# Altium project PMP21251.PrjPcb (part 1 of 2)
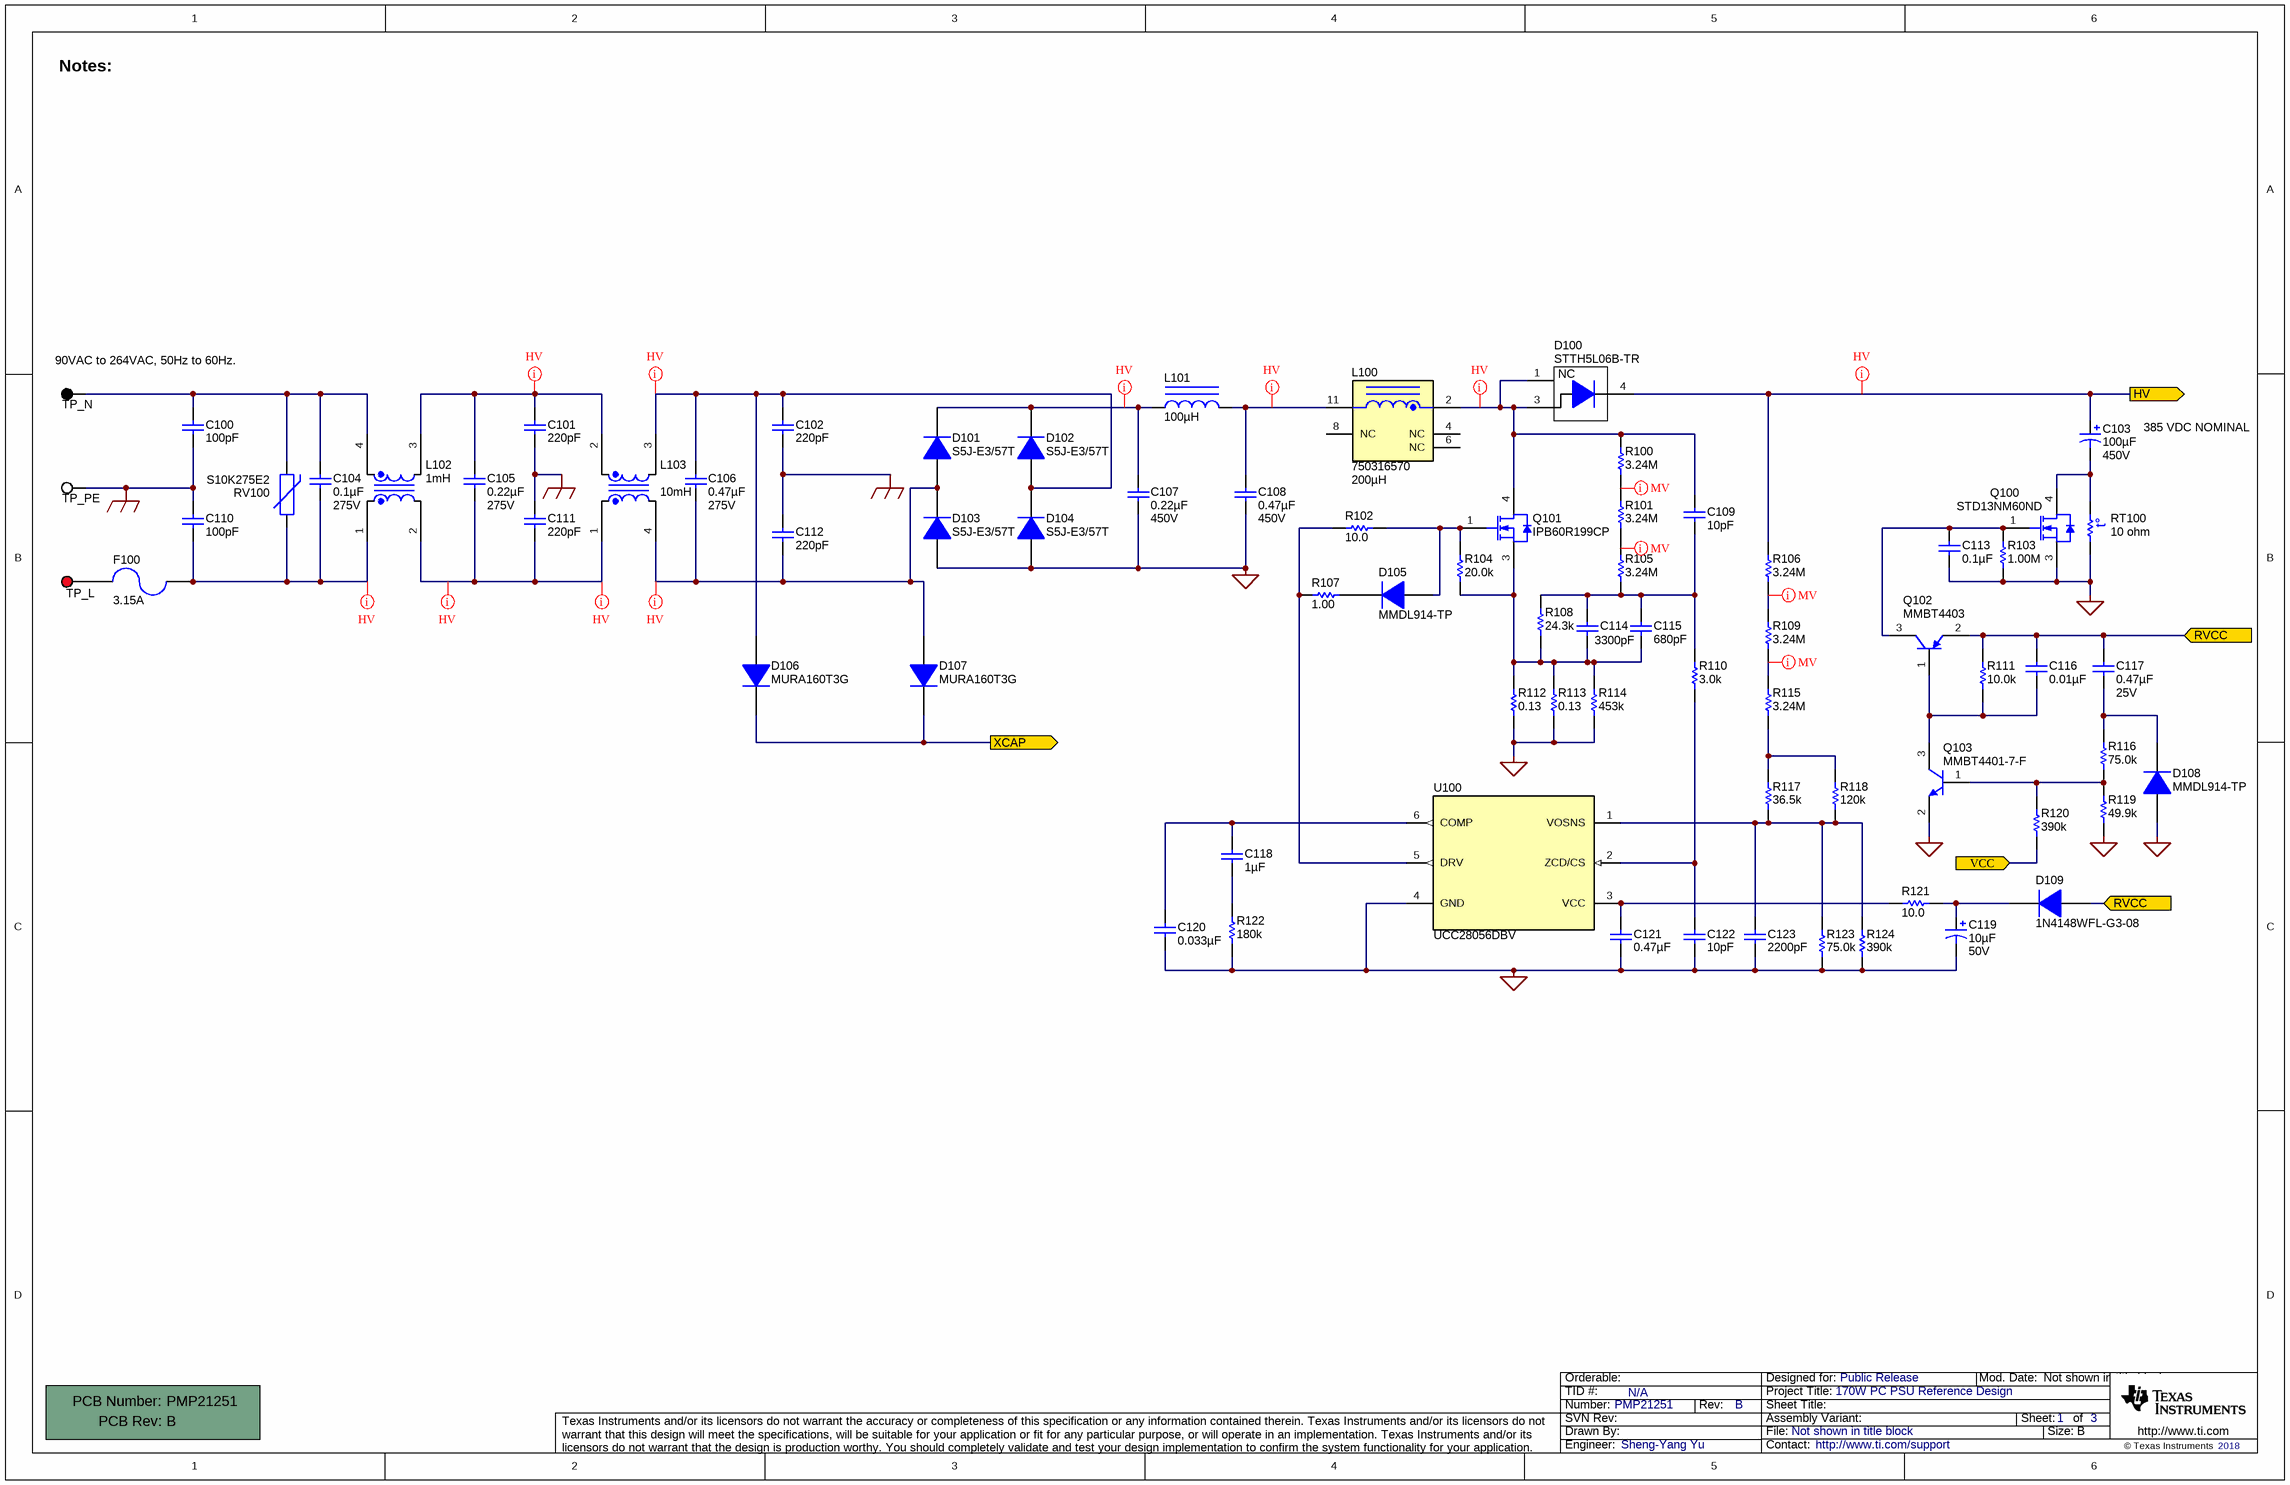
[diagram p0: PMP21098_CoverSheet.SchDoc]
CopyrightYear: 2018; PCB_Layout: Sheng-Yang Yu; PCB_Rev: B; PRJ_Customer: Public Release; PRJ_Engineer: Sheng-Yang Yu; PRJ_Number: PMP21251; PRJ_Title: 170W PC PSU Reference Design; SCH_Rev: B; TechSupport: http://www.ti.com/support; TID: N/A
3 sheets, 198 parts. Net scope: flat (ports and power ports of the same name join across sheets).
Board file: PMP21098_PCB.PcbDoc
Sheets:
  PMP21098_CoverSheet.SchDoc
  PMP21098_BlankSheet.SchDoc
  PMP21098_EVM_Hardware.SchDoc

## Sheet PMP21098_CoverSheet.SchDoc
size 431 x 279 mm; Date: Not shown in title block; ApprovedBy: Not shown in title block; CheckedBy: Not shown in title block; Author: Not shown in title block; CompanyName: Not shown in title block; Engineer: Not shown in title block; Organization: Not shown in title block; Address1: Not shown in title block; Address2: Not shown in title block; Address3: Not shown in title block; Address4: Not shown in title block; DocumentNumber: 1; Revision: Use project parameter SCH_Rev; SheetNumber: 1; SheetTotal: 3; PageSetup: Record=PageOptions¦CenterHorizontal=True¦CenterVertical=True¦PrintScale=1.00¦XCorrection=1.00¦YCorrection=1.00¦PrintKind=0¦BorderSize=5000000¦LeftOffset=0¦BottomOffset=0¦Orientation=2¦PaperLength=1000¦PaperWidth=1000¦Scale=100¦PaperSource=15¦PrintQuality=600¦MediaType=1¦DitherType=10¦PaperKind=Letter¦PrintScaleMode=1

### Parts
!PCB100  Printed Circuit Board  (value not drawn)  (mechanical)
C100  ValueDisplayed: 100pF  [DE1_600x400x900]  (hidden comment: DE1B3RA101KN4AN01F)
C101  ValueDisplayed: 220pF  [DE1_600x400x900]  (hidden comment: DE1B3RA101KN4AN01F)
C102  ValueDisplayed: 220pF  [DE1_600x400x900]  (hidden comment: DE1B3RA101KN4AN01F)
C103  ValueDisplayed: 100µF  Value2: 450V  [HXG_2200x4500]  (hidden comment: EKMQ451VSN101MP30S)
C104  ValueDisplayed: 0.1µF  VAC_X: 275V  [WCAP-FTX2_1300x700x1200]  (hidden comment: 890324023023CS)
C105  ValueDisplayed: 0.22µF  VAC_X: 275V  [WCAP-FTX2_1300x700x1200]  (hidden comment: 890324023028CS)
C106  ValueDisplayed: 0.47µF  VAC_X: 275V  [WCAP-FTX2_1500x1000x1600]  (hidden comment: 890324024005)
C107  ValueDisplayed: 0.22µF  Value2: 450V  [MPK_1800x650]  (hidden comment: ECW-FD2W224KQ)
C108  ValueDisplayed: 0.47µF  Value2: 450V  [MPK_1800x650]  (hidden comment: 450MPK474J)
C109  ValueDisplayed: 10pF  [0805_HV]  (hidden comment: VJ0805A100JXGAT5Z)
C110  ValueDisplayed: 100pF  [DE1_600x400x900]  (hidden comment: DE1B3RA101KN4AN01F)
C111  ValueDisplayed: 220pF  [DE1_600x400x900]  (hidden comment: DE1B3RA101KN4AN01F)
C112  ValueDisplayed: 220pF  [DE1_600x400x900]  (hidden comment: DE1B3RA101KN4AN01F)
C113  ValueDisplayed: 0.1µF  [0603]  (hidden comment: GRM188R61E104KA01D)
C114  ValueDisplayed: 3300pF  [0603]  (hidden comment: 06031C332JAT2A)
C115  ValueDisplayed: 680pF  [0603]  (hidden comment: GRM1885C1H681JA01D)
C116  ValueDisplayed: 0.01µF  [0603]  (hidden comment: 885012206040)
C117  ValueDisplayed: 0.47µF  Value2: 25V  [0805_HV]  (hidden comment: 08053D474KAT2A)
C118  ValueDisplayed: 1µF  [0603]  (hidden comment: C0603C105K3RACTU)
C119  ValueDisplayed: 10µF  Value2: 50V  [NHG_500x1100]  (hidden comment: ECA-1HHG100)
C120  ValueDisplayed: 0.033µF  [0603]  (hidden comment: C0603C333J3RACTU)
C121  ValueDisplayed: 0.47µF  [1206_180]  (hidden comment: CGA5L2X7R1H474K160AA)
C122  ValueDisplayed: 10pF  [0603]  (hidden comment: 0603ZC100KAT2A)
C123  ValueDisplayed: 2200pF  [0603]  (hidden comment: C0603C222K5RACTU)
D100  STTH5L06B-TR  [DPAK]
D101  S5J-E3/57T  [SMC]
D102  S5J-E3/57T  [SMC]
D103  S5J-E3/57T  [SMC]
D104  S5J-E3/57T  [SMC]
D105  MMDL914-TP  [SOD-323]
D106  MURA160T3G  [SMA]
D107  MURA160T3G  [SMA]
D108  MMDL914-TP  [SOD-323]
D109  1N4148WFL-G3-08  [SOD-123FL]
F100  Irating_A: 3.15A  [FUSE_372]  (hidden comment: 37213150001)
L100  750316570  ValueDisplayed: 200µH  [750316570]
L101  ValueDisplayed: 100µH  [IND_7447020]  (hidden comment: 7447021)
L102  ValueDisplayed: 1mH  [WE-CMB_XS]  (hidden comment: 744821201)
L103  ValueDisplayed: 10mH  [WE-CMB_M]  (hidden comment: 744823210)
Q100  STD13NM60ND  [DPAK]
Q101  IPB60R199CP  [DDPAK]
Q102  MMBT4403  [SOT-23]
Q103  MMBT4401-7-F  [SOT-23]
R100  ValueDisplayed: 3.24M  [1206]  (hidden comment: CRCW12063M24FKEA)
R101  ValueDisplayed: 3.24M  [1206]  (hidden comment: CRCW12063M24FKEA)
R102  ValueDisplayed: 10.0  [0603]  (hidden comment: CRCW060310R0FKEA)
R103  ValueDisplayed: 1.00M  [0603]  (hidden comment: CRCW06031M00FKEA)
R104  ValueDisplayed: 20.0k  [0805_HV]  (hidden comment: CRCW080520K0FKEA)
R105  ValueDisplayed: 3.24M  [1206]  (hidden comment: CRCW12063M24FKEA)
R106  ValueDisplayed: 3.24M  [1206]  (hidden comment: CRCW12063M24FKEA)
R107  ValueDisplayed: 1.00  [0603]  (hidden comment: CRCW06031R00FKEA)
R108  ValueDisplayed: 24.3k  [0603]  (hidden comment: CRCW060324K3FKEA)
R109  ValueDisplayed: 3.24M  [1206]  (hidden comment: CRCW12063M24FKEA)
R110  ValueDisplayed: 3.0k  [0603]  (hidden comment: CRCW06033K00JNEA)
R111  ValueDisplayed: 10.0k  [0603]  (hidden comment: CRCW060310K0FKEA)
R112  ValueDisplayed: 0.13  [1206]  (hidden comment: CSR1206FTR130)
R113  ValueDisplayed: 0.13  [1206]  (hidden comment: CSR1206FTR130)
R114  ValueDisplayed: 453k  [1206]  (hidden comment: CRCW1206453KFKEA)
R115  ValueDisplayed: 3.24M  [1206]  (hidden comment: CRCW12063M24FKEA)
R116  ValueDisplayed: 75.0k  [0603]  (hidden comment: CRCW060375K0FKEA)
R117  ValueDisplayed: 36.5k  [0603]  (hidden comment: CRCW060336K5FKEA)
R118  ValueDisplayed: 120k  [0603]  (hidden comment: RC0603FR-07120KL)
R119  ValueDisplayed: 49.9k  [0603]  (hidden comment: CRCW060349K9FKEA)
R120  ValueDisplayed: 390k  [0603]  (hidden comment: RC0603FR-07390KL)
R121  ValueDisplayed: 10.0  [0805_HV]  (hidden comment: CRCW080510R0FKEA)
R122  ValueDisplayed: 180k  [0603]  (hidden comment: RC0603FR-07180KL)
R123  ValueDisplayed: 75.0k  [0603]  (hidden comment: CRCW060375K0FKEA)
R124  ValueDisplayed: 390k  [0603]  (hidden comment: RC0603FR-07390KL)
RT100  value 10 ohm  [THERM_B57236S0]  (hidden comment: B57236S0100M000)
RV100  S10K275E2  [VAR_S10K275E2]
TP_L  5010  [Keystone5010]  (value not drawn)
TP_N  5011  [Keystone5011]  (value not drawn)
TP_PE  5012  [Keystone5012]  (value not drawn)
U100  UCC28056DBV  [DBV0006A_N]

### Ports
HV (out), RVCC (in), VCC (in), XCAP (out)

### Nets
GND: C107.1 C108.1 C113.2 C119.2(-) C120.2 C121.2 C122.2 C123.2 D103.2(A) D104.2(A) D108.2(A) Q100.3(S) Q103.2(E) R103.1 R112.1 R113.1 R114.1 R119.1 R122.1 R123.1 R124.1 RT100.1 U100.4(GND)
PE: C100.2 C101.2 C102.2 C110.1 C111.1 C112.1 TP_PE.1
HV: C103.1(+) D100.4(K) R106.2 ; port HV
RVCC: C116.1 C117.1 D109.2(A) Q102.2(E) R111.2 ; port RVCC
VCC: R120.1 ; port VCC
XCAP: D106.1(K) D107.1(K) ; port XCAP
NetC100_1: C100.1 C104.1 L102.4 RV100.2 TP_N.1
NetC101_1: C101.1 C105.1 L102.3 L103.2
NetC102_1: C102.1 C106.1 D102.2(A) D104.1(K) D106.2(A) L103.3
NetC103_2: C103.2(-) Q100.4(D) RT100.2
NetC104_2: C104.2 C110.2 F100.2 L102.1 RV100.1
NetC105_2: C105.2 C111.2 L102.2 L103.1
NetC106_2: C106.2 C112.2 D101.2(A) D103.1(K) D107.2(A) L103.4
NetC107_2: C107.2 D101.1(K) D102.1(K) L101.1
NetC108_2: C108.2 L100.11 L101.2
NetC109_1: C109.1 C114.1 C115.1 R105.1 R108.2 R110.1
NetC109_2: C109.2 D100.1(NC) D100.3(A) L100.2 Q101.4(D) R100.2
NetC113_1: C113.1 Q100.1(G) Q102.3(C) R103.2
NetC114_2: C114.2 C115.2 Q101.3(S) R104.1 R108.1 R112.2 R113.2 R114.2
NetC116_2: C116.2 Q102.1(B) Q103.3(C) R111.1
NetC117_2: C117.2 D108.1(K) R116.2
NetC118_1: C118.1 C120.1 U100.6(COMP)
NetC118_2: C118.2 R122.2
NetC119_1: C119.1(+) D109.1(K) R121.2
NetC121_1: C121.1 R121.1 U100.3(VCC)
NetC122_1: C122.1 R110.2 U100.2(ZCD/CS)
NetC123_1: C123.1 R117.1 R118.1 R123.2 R124.2 U100.1(VOSNS)
NetD105_1: D105.1(K) R107.2
NetD105_2: D105.2(A) Q101.1(G) R102.2 R104.2
NetF100_1: F100.1 TP_L.1
NetQ103_1: Q103.1(B) R116.1 R119.2 R120.2
NetR100_1: R100.1 R101.2
NetR101_1: R101.1 R105.2
NetR102_1: R102.1 R107.1 U100.5(DRV)
NetR106_1: R106.1 R109.2
NetR109_1: R109.1 R115.2
NetR115_1: R115.1 R117.2 R118.2

Not connected (* = marked no-connect by the designer): L100 4(NC) 6(NC) 8(NC)

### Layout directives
net class HV: HV, NetC101_1, NetC102_1, NetC104_2, NetC105_2, NetC106_2, NetC107_2, NetC108_2, NetC109_2
net class MV: (no net found under the mark), NetR100_1, NetR106_1, NetR109_1

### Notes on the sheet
- Notes:
- (near TP_N) 90VAC to 264VAC, 50Hz to 60Hz.
- 385 VDC NOMINAL

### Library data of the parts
!PCB100 = PCB: Manufacturer: Any; PartNumber: PMP21251; SymbolCreator: a0412235
C100 = CMP-0077651-2: CAP, CERM, 100 pF, X1 440 VAC/Y1 250 VAC, +/- 10%, B, D6xT4mm; Manufacturer: MuRata; TaMax_C: 125°C; SizeX_mm: 10.6; SizeY_mm: 4.0; TaMin_C: -40°C; CompType: Capacitor; SizeZ_mm: 9.0; AEC Qualified: N; Value: 100pF; SizeArea_mm2: 42.4; AEC Category: Q200; SizeAreaWB_mm2: 75.6; U/M: EA; Cap_Case: 6x4x9mm; AC_Safety: X1Y1; VAC_X: 440; VAC_Y: 250
C101 C102 C111 C112 = CMP-0077651-2: CAP CER 220PF 250V RAD; PartNumber: DE1B3RA221KN4AN01F; Manufacturer: MuRata; TaMax_C: 125°C; SizeX_mm: 10.6; SizeY_mm: 4.0; TaMin_C: -40°C; CompType: Capacitor; SizeZ_mm: 9.0; AEC Qualified: N; SizeArea_mm2: 42.4; AEC Category: Q200; SizeAreaWB_mm2: 75.6; U/M: EA; Tolerance_%: 10%; TempCo: B; Cap_Case: 6x4x9mm; Cap_F: 100pF; AC_Safety: X1Y1; VAC_X: 440; VAC_Y: 250
C103 = 450HXG180MEFCSN22X45: CAP ALUM 100UF 20% 450V SNAP; Manufacturer: United Chemi-Con; Polarized: Y; CompType: Capacitor; U/M: EA; Cap_F: 0.0001; Tolerance_%: 20; VDC_V: 450; TaMin_C: -25; TaMax_C: 105; Cap_Case: 22x45mm; AEC Category: Q200; AEC Qualified: N; Green_Lifecycle: Not Set; Green_REACh: Incomplete
C104 = 890324023025CS: CAP, Film, 0.1 µF, X2 275 VAC, +/- 10%, TH; Manufacturer: Wurth Elektronik; Polarized: N; CompType: Capacitor; Value: 0.1uF; U/M: EA; Cap_F: 0.00000015; Tolerance_%: 10; TaMin_C: -40; TaMax_C: 105; Cap_Case: 13x7x12; SizeAreaWB_mm2: 135; SizeArea_mm2: 91; SizeX_mm: 13; SizeY_mm: 7; SizeZ_mm: 12.5; AEC Category: Q200; Green_Lifecycle: Not Set; Green_REACh: Incomplete
C105 = 890324023025CS: CAP, Film, 0.22 µF, X2 275 VAC, +/- 10%, TH; Manufacturer: Wurth Elektronik; Polarized: N; CompType: Capacitor; Value: 0.22uF; U/M: EA; Cap_F: 0.00000015; Tolerance_%: 10; TaMin_C: -40; TaMax_C: 105; Cap_Case: 13x7x12; SizeAreaWB_mm2: 135; SizeArea_mm2: 91; SizeX_mm: 13; SizeY_mm: 7; SizeZ_mm: 12.5; AEC Category: Q200; Green_Lifecycle: Not Set; Green_REACh: Incomplete
C106 = 890324024005: CAP, Film, 0.47 µF, X2 275 VAC, +/- 10%, TH; Manufacturer: Wurth Elektronik; Polarized: N; CompType: Capacitor; Value: 0.47uF; U/M: EA; Cap_F: 0.00000047; Tolerance_%: 10; TaMin_C: -40; TaMax_C: 105; Cap_Case: 15x10x16mm; SizeAreaWB_mm2: 204; SizeArea_mm2: 150; SizeX_mm: 15; SizeZ_mm: 16.5; AEC Category: Q200; Green_Lifecycle: Not Set; Green_REACh: Incomplete
C107 = 450MPK474J: 0.22µF ±10% Film Capacitor 450V Polypropylene (PP), Metallized Radial; Manufacturer: Panasonic Electronic Components; Polarized: N; Value: 0.22uF; U/M: EA; Cap_F: 0.00000047; Tolerance_%: 5; Value1: Unknown; VDC_V: 450; TaMin_C: -40; TaMax_C: 105; Cap_Case: 18x6.5mm; AEC Category: Q200
C108 = 450MPK474J: CAP, Film, 0.47 µF, 450 V, +/- 5%, TH; Manufacturer: Rubycon; Polarized: N; CompType: Capacitor; Value: 0.47uF; U/M: EA; Cap_F: 0.00000047; Tolerance_%: 5; Value1: Unknown; VDC_V: 450; TaMin_C: -40; TaMax_C: 105; Cap_Case: 18x6.5mm; AEC Category: Q200
C109 = VJ0805A100JXGAT5Z: CAP, CERM, 10 pF, 1000 V,+/- 5%, C0G/NP0, 0805; Manufacturer: Vishay-Vitramon; Polarized: N; CompType: Capacitor; Value: 10pF; U/M: EA; Cap_F: 0.00000000001; Tolerance_%: 5; Value1: Unknown; VDC_V: 1000; Value2: 1000V; TaMin_C: -55; TaMax_C: 125; Cap_Case: 0805; SizeArea_mm2: 2.5; SizeAreaWB_mm2: 6.75; SizeX_mm: 2; SizeY_mm: 1.25; SizeZ_mm: 1.45; AEC Category: Q200
C110 = CMP-0077651-2: CAP, CERM, 100 pF, X1 440 VAC/Y1 250 VAC, +/- 10%, B, D6xT4mm; Manufacturer: MuRata; TaMax_C: 125°C; SizeX_mm: 10.6; SizeY_mm: 4.0; TaMin_C: -40°C; SizeZ_mm: 9.0; AEC Qualified: N; Value: 100pF; SizeArea_mm2: 42.4; AEC Category: Q200; SizeAreaWB_mm2: 75.6; U/M: EA; Cap_Case: 6x4x9mm; AC_Safety: X1Y1; VAC_X: 440; VAC_Y: 250
C113 = GRM188R61E104KA01D: CAP, CERM, 0.1 µF, 25 V,+/- 10%, X5R, 0603; Manufacturer: MuRata; Polarized: N; CompType: Capacitor; Value: 0.1uF; U/M: EA; Cap_F: 0.0000001; Tolerance_%: 10; VDC_V: 25; Value2: 25V; TaMin_C: -55; TaMax_C: 85; SizeArea_mm2: 1.28; SizeAreaWB_mm2: 4.68; SizeX_mm: 1.6; SizeY_mm: 0.8; SizeZ_mm: 1; AEC Category: Q200; Green_Lifecycle: Active; Green_REACh: Passed
C114 = 06031C332JAT2A: CAP, CERM, 3300 pF, 100 V,+/- 5%, X7R, 0603; Manufacturer: AVX; Polarized: N; CompType: Capacitor; Value: 3300pF; U/M: EA; Cap_F: 0.0000000033; Tolerance_%: 5; ESR_ohm: 0.159; Value1: 0.159 ohm; VDC_V: 100; Value2: 100V; TaMin_C: -55; TaMax_C: 125; SizeArea_mm2: 1.28; SizeAreaWB_mm2: 4.68; SizeX_mm: 1.6; SizeY_mm: 0.8; SizeZ_mm: 1; AEC Category: Q200; Green_Lifecycle: Active; Green_REACh: Passed
C115 = GRM1885C1H681JA01D: CAP, CERM, 680 pF, 50 V,+/- 5%, C0G/NP0, 0603; Manufacturer: MuRata; Polarized: N; CompType: Capacitor; Value: 680pF; U/M: EA; Cap_F: 0.00000000068; Tolerance_%: 5; VDC_V: 50; Value2: 50V; TaMin_C: -55; TaMax_C: 125; SizeArea_mm2: 1.28; SizeAreaWB_mm2: 4.68; SizeX_mm: 1.6; SizeY_mm: 0.8; SizeZ_mm: 1; AEC Category: Q200
C116 = 885012206040: CAP, CERM, 0.01 µF, 16 V,+/- 10%, X7R, 0603; Manufacturer: Wurth Elektronik; Polarized: N; CompType: Capacitor; Value: 0.01uF; U/M: EA; Cap_F: 0.00000001; Tolerance_%: 10; VDC_V: 16; Value2: 16V; TaMin_C: -55; TaMax_C: 125; SizeArea_mm2: 1.28; SizeAreaWB_mm2: 4.68; SizeX_mm: 1.6; SizeY_mm: 0.8; SizeZ_mm: 1; AEC Category: Q200; Green_Lifecycle: Active; Green_REACh: Passed
C117 = 08053D474KAT2A: CAP, CERM, 0.47 µF, 25 V,+/- 10%, X5R, 0805; Manufacturer: AVX; Polarized: N; CompType: Capacitor; Value: 0.47uF; U/M: EA; Cap_F: 0.00000047; Tolerance_%: 10; ESR_ohm: 0.017; Value1: 0.017 ohm; VDC_V: 25; TaMin_C: -55; TaMax_C: 85; Cap_Case: 0805; SizeArea_mm2: 2.5; SizeAreaWB_mm2: 6.75; SizeX_mm: 2; SizeY_mm: 1.25; SizeZ_mm: 1.45; AEC Category: Q200; Green_Lifecycle: Active; Green_REACh: Passed
C118 = C0603C105K3RACTU: CAP, CERM, 1 µF, 25 V,+/- 10%, X7R, 0603; Manufacturer: Kemet; Polarized: N; CompType: Capacitor; Value: 1uF; U/M: EA; Cap_F: 0.000001; Tolerance_%: 10; VDC_V: 25; Value2: 25V; TaMin_C: -55; TaMax_C: 125; SizeArea_mm2: 1.28; SizeAreaWB_mm2: 4.68; SizeX_mm: 1.6; SizeY_mm: 0.8; SizeZ_mm: 1; AEC Category: Q200; Green_Lifecycle: Active; Green_REACh: Passed
C119 = ECA-1HHG100: CAP, AL, 10 µF, 50 V, +/- 20%, TH; Manufacturer: Panasonic; Polarized: Y; CompType: Capacitor; Value: 10uF; U/M: EA; Cap_F: 0.00001; Tolerance_%: 20; VDC_V: 50; IRMS_A: 0.039; TaMin_C: -55; TaMax_C: 105; Cap_Case: 5x11mm; SizeAreaWB_mm2: 49; SizeArea_mm2: 25; SizeX_mm: 5; SizeZ_mm: 12; AEC Category: Q200; AEC Qualified: N
C120 = C0603C333J3RACTU: CAP, CERM, 0.033 µF, 25 V,+/- 5%, X7R, 0603; Manufacturer: Kemet; Polarized: N; CompType: Capacitor; Value: 0.033uF; U/M: EA; Cap_F: 0.000000033; Tolerance_%: 5; VDC_V: 25; Value2: 25V; TaMin_C: -55; TaMax_C: 125; SizeArea_mm2: 1.28; SizeAreaWB_mm2: 4.68; SizeX_mm: 1.6; SizeY_mm: 0.8; SizeZ_mm: 1; AEC Category: Q200
C121 = CGA5L2X7R1H474K160AA: CAP, CERM, 0.47 µF, 50 V,+/- 10%, X7R, AEC-Q200 Grade 1, 1206; Manufacturer: TDK; Polarized: N; CompType: Capacitor; Value: 0.47uF; U/M: EA; Cap_F: 0.00000047; Tolerance_%: 10; ESR_ohm: 0.009426; Value1: 0.009426 ohm; VDC_V: 50; Value2: 50V; IRMS_A: 2.37046; TaMin_C: -55; TaMax_C: 125; Cap_Case: 1206; SizeArea_mm2: 5.12; SizeAreaWB_mm2: 10.92; SizeX_mm: 3.2; SizeY_mm: 1.6; SizeZ_mm: 1.8; AEC Category: Q200; AEC Qualified: Y; AEC Grade: 1
C122 = 0603ZC100KAT2A: CAP, CERM, 10 pF, 10 V,+/- 10%, X7R, 0603; Manufacturer: AVX; Polarized: N; CompType: Capacitor; Value: 10pF; U/M: EA; Cap_F: 0.00000000001; Tolerance_%: 10; Value1: Unknown; Value2: 10V; TaMin_C: -55; TaMax_C: 125; SizeArea_mm2: 1.28; SizeAreaWB_mm2: 4.68; SizeX_mm: 1.6; SizeY_mm: 0.8; SizeZ_mm: 1; AEC Category: Q200
C123 = C0603C222K5RACTU: CAP, CERM, 2200 pF, 50 V,+/- 10%, X7R, 0603; Manufacturer: Kemet; Polarized: N; CompType: Capacitor; Value: 2200pF; U/M: EA; Cap_F: 0.0000000022; Tolerance_%: 10; VDC_V: 50; Value2: 50V; TaMin_C: -55; TaMax_C: 125; SizeArea_mm2: 1.28; SizeAreaWB_mm2: 4.68; SizeX_mm: 1.6; SizeY_mm: 0.8; SizeZ_mm: 1; AEC Category: Q200; Green_Lifecycle: Active; Green_REACh: Passed
D100 = STTH5R06B-TR: DIODE GEN PURP 600V 5A DPAK; Manufacturer: STMicroelectronics; SymbolCreator: a0412235; U/M: EA; Vf_V: 2.9; Value2: 2.9V; Io_A: 5; Vr_V: 600; TJmax_C: 175; RJC_CperW: 3; Type: High Voltage Rectifier; AEC Category: Q101
D101-D104 = S5J-E3/57T: Diode, P-N, 600 V, 5 A, SMC; Manufacturer: Vishay-Semiconductor; U/M: EA; Vf_V: 1.15; Value: 600V; Value1: 5A; Value2: 1.15V; Io_A: 5; Vr_V: 600; TJmax_C: 150; RJC_CperW: 10; SizeAreaWB_mm2: 83.2686; SizeArea_mm2: 50.5686; SizeX_mm: 8.13; SizeY_mm: 6.22; SizeZ_mm: 2.6; AEC Category: Q101; Green_Lifecycle: Not Set; Green_REACh: Incomplete
D105 D108 = MMDL914-TP: Diode, Switching, 100 V, 0.2 A, SOD-323; Manufacturer: Micro Commercial Components; U/M: EA; Vf_V: 1; Value: 100V; Value1: 0.2A; Value2: 1V; Io_A: 0.2; Vr_V: 100; TJmax_C: 150; SizeAreaWB_mm2: 8.695; SizeArea_mm2: 3.645; SizeX_mm: 2.7; SizeY_mm: 1.35; AEC Category: Q101
D106 D107 = MURA160T3G: Diode, Ultrafast, 600V, 1A, SMA; Manufacturer: ON Semiconductor; Value: 1.05V; U/M: EA; Vf_V: 1.05; Io_A: 1; Vr_V: 600; TJmax_C: 175
D109 = 1N4148WFL-G3-08: Diode, Switching, 100 V, 0.15 A, SOD-123FL; Manufacturer: Vishay-Semiconductor; U/M: EA; Vf_V: 1.2; Value: 100V; Value1: 0.15A; Value2: 1.2V; Io_A: 0.15; Vr_V: 100; TJmax_C: 150; SizeAreaWB_mm2: 12.19; SizeArea_mm2: 5.94; SizeX_mm: 3.6; SizeY_mm: 1.65; SizeZ_mm: 0.98; AEC Category: Q101; Green_Lifecycle: Not Set; Green_REACh: Incomplete
F100 = 37213150001: Fuse, 3.15 A, 250VAC/VDC, TH; Manufacturer: Littelfuse; VDC_V: 250
L100 = 750316570: Inductor, 200 µH, 0.235 ohm, TH; Manufacturer: Wurth Elektronik; SymbolCreator: Altium; Ind_H: 200.0E-6; Value: 200uH; DCR_ohm: 0.235; Value2: A; SizeAreaWB_mm2: 792.9856; SizeArea_mm2: 684.3456; SizeX_mm: 26.16; SizeZ_mm: 19.05; AEC Category: Q200; AEC Qualified: N; Green_Lifecycle: Not Set; Green_REACh: Incomplete
L101 = 7447020: 100µH Unshielded Toroidal Inductor 2A 80 mOhm Max Radial; Manufacturer: Wurth Elektronik; Ind_H: 100.0E-6; Imax_A: 1; Irms: 2.5A @ 40C rise; DCR_ohm: 0.16; Value1: 0.16 ohm; Material: Powdered Iron; SizeAreaWB_mm2: 169.1; SizeArea_mm2: 118.5; SizeX_mm: 7.5; SizeY_mm: 15.8; AEC Category: Q200
L102 = 744821201: Coupled inductor, 1 mH, 2 A, 0.045 ohm, TH; Manufacturer: Wurth Elektronik; SymbolCreator: a0412235; SizeAreaWB_mm2: 161.5; SizeArea_mm2: 112.5; SizeX_mm: 15; SizeY_mm: 7.5; SizeZ_mm: 20.5; Value: 1mH; Ind_H: 1.0E-3; DCR_ohm: 0.045; AEC Category: Q200; AEC Qualified: N
L103 = 744823210: Coupled inductor, 10 mH, 2 A, 0.125 ohm, TH; Manufacturer: Wurth Elektronik; SymbolCreator: a0799628; SizeAreaWB_mm2: 513; SizeArea_mm2: 425; SizeX_mm: 25; SizeY_mm: 17; SizeZ_mm: 26.5; Value: 10mH; Ind_H: 10.0E-3; DCR_ohm: 0.125; AEC Category: Q200
Q100 = STD13NM60ND: MOSFET, N-CH, 600 V, 11 A, DPAK; Manufacturer: STMicroelectronics; Alternate Manufacturer: None; U/M: EA; ChType: N; Value: 600V; VdsMax_V: 600; Value1: ? ohm; Value2: 24.5 nC; QgTyp_nC: 24.5; Vgs_V: 25; IdsMax_A: 11; SizeAreaWB_mm2: 101.7114; SizeArea_mm2: 64.8114; SizeX_mm: 9.91; SizeY_mm: 6.54; SizeZ_mm: 2.29; AEC Category: Q101; Green_Lifecycle: Not Set; Green_REACh: Incomplete
Q101 = IPB60R199CPATMA1: MOSFET, N-CH, 600 V, 16 A, DDPAK; Manufacturer: Infineon Technologies; Alternate Manufacturer: None; U/M: EA; ChType: N; Value: 600V; VdsMax_V: 600; Value1: ? ohm; Value2: 32 nC; QgTyp_nC: 32; Vgs_V: 20; IdsMax_A: 16; SizeAreaWB_mm2: 209.6992; SizeArea_mm2: 154.8892; SizeX_mm: 15.245; SizeY_mm: 10.16; SizeZ_mm: 4.445; AEC Category: Q101
Q102 = MMBT4403, Fairchild Semiconductor: Transistor, PNP, 40 V, 0.6 A, SOT-23; CompType: BJT; PNP: 1; NPN: 0; Vceo_V: 40; Vcesat1_V: 0.75; Value: 40 V; IcRated_A: 0.6; Value1: 0.6 A; HfeMax: 500; TaMin_C: -55; TaMax_C: 150; SizeAreaWB_mm2: 14; SizeArea_mm2: 7.5; SizeX_mm: 2.5; SizeY_mm: 3; SizeZ_mm: 1.1; U/M: EA; AEC Category: Q101; Green_Lifecycle: Active; Green_REACh: Passed
Q103 = MMBT4401-7-F, Diodes Inc.: Transistor, NPN, 40 V, 0.15 A, SOT-23; CompType: BJT; PNP: 0; NPN: 1; Vceo_V: 40; Vcesat1_V: 0.4; Value: 40 V; IcRated_A: 0.15; Value1: 0.15 A; HfeMax: 300; TaMin_C: -55; TaMax_C: 150; SizeAreaWB_mm2: 14; SizeArea_mm2: 7.5; SizeX_mm: 2.5; SizeY_mm: 3; SizeZ_mm: 1.1; U/M: EA; AEC Category: Q101; Green_Lifecycle: Active; Green_REACh: Passed
R100 R101 R105 R106 R109 R115 = CRCW12063M24FKEA: RES, 3.24 M, 1%, 0.25 W, 1206; Manufacturer: Vishay-Dale; CompType: Resistor; Value: 3.24Meg; Res_ohm: 3240000; Value_Code: 3M24; Tolerance_%: 1; Power_W: 0.25; Value2: 0.25W; VDC_V: 200; TempCo: 100 ppm/C; SizeArea_mm2: 5.12; SizeX_mm: 3.2; SizeY_mm: 1.6; SizeZ_mm: 1.35; EIA_Code: E96; U/M: EA; AEC Category: Q200
R102 = CRCW060310R0FKEA: RES, 10.0, 1%, 0.1 W, 0603; Manufacturer: Vishay-Dale; CompType: Resistor; Value: 10.0; Res_ohm: 10; Value_Code: 10R0; Tolerance_%: 1; Power_W: 0.1; Value2: 0.1W; VDC_V: 75; TempCo: 100 ppm/C; SizeArea_mm2: 1.28; SizeX_mm: 1.6; SizeY_mm: 0.8; EIA_Code: E96; U/M: EA; AEC Category: Q200; Green_Lifecycle: Active; Green_REACh: Passed
R103 = CRCW06031M00FKEA: RES, 1.00 M, 1%, 0.1 W, 0603; Manufacturer: Vishay-Dale; CompType: Resistor; Value: 1.00Meg; Res_ohm: 1000000; Value_Code: 1M00; Tolerance_%: 1; Power_W: 0.1; Value2: 0.1W; VDC_V: 75; TempCo: 100 ppm/C; SizeArea_mm2: 1.28; SizeX_mm: 1.6; SizeY_mm: 0.8; EIA_Code: E96; U/M: EA; AEC Category: Q200; Green_Lifecycle: Active; Green_REACh: Passed
R104 = CRCW080520K0FKEA: RES, 20.0 k, 1%, 0.125 W, 0805; Manufacturer: Vishay-Dale; CompType: Resistor; Value: 20.0k; Res_ohm: 20000; Value_Code: 20k0; Tolerance_%: 1; Power_W: 0.125; Value2: 0.125W; VDC_V: 150; TempCo: 100 ppm/C; SizeArea_mm2: 2.5; SizeX_mm: 2; SizeY_mm: 1.25; SizeZ_mm: 1.45; EIA_Code: E96; U/M: EA; AEC Category: Q200; Green_Lifecycle: Active; Green_REACh: Passed
R107 = CRCW06031R00FKEA: RES, 1.00, 1%, 0.1 W, 0603; Manufacturer: Vishay-Dale; CompType: Resistor; Value: 1.00; Res_ohm: 1; Value_Code: 1R00; Power_W: 0.1; Value2: 0.1W; VDC_V: 75; TempCo: 100 ppm/C; SizeArea_mm2: 1.28; SizeX_mm: 1.6; SizeY_mm: 0.8; EIA_Code: E96; U/M: EA; AEC Category: Q200; Green_Lifecycle: Active; Green_REACh: Passed
R108 = CRCW060324K3FKEA: RES, 24.3 k, 1%, 0.1 W, 0603; Manufacturer: Vishay-Dale; CompType: Resistor; Value: 24.3k; Res_ohm: 24300; Value_Code: 24k3; Tolerance_%: 1; Power_W: 0.1; Value2: 0.1W; VDC_V: 75; TempCo: 100 ppm/C; SizeArea_mm2: 1.28; SizeX_mm: 1.6; SizeY_mm: 0.8; EIA_Code: E96; U/M: EA; AEC Category: Q200; Green_Lifecycle: Active; Green_REACh: Passed
R110 = CRCW06033K00JNEA: RES, 3.0 k, 5%, 0.1 W, 0603; Manufacturer: Vishay-Dale; CompType: Resistor; Value: 3.0k; Res_ohm: 3000; Value_Code: 3k00; Tolerance_%: 5; Power_W: 0.1; Value2: 0.1W; VDC_V: 75; TempCo: 200 ppm/C; SizeArea_mm2: 1.28; SizeX_mm: 1.6; SizeY_mm: 0.8; SizeZ_mm: 1; EIA_Code: E24; U/M: EA; AEC Category: Q200; Green_Lifecycle: Active; Green_REACh: Passed
R111 = CRCW060310K0FKEA: RES, 10.0 k, 1%, 0.1 W, 0603; Manufacturer: Vishay-Dale; CompType: Resistor; Value: 10.0k; Res_ohm: 10000; Value_Code: 10k0; Tolerance_%: 1; Power_W: 0.1; Value2: 0.1W; VDC_V: 75; TempCo: 100 ppm/C; SizeArea_mm2: 1.28; SizeX_mm: 1.6; SizeY_mm: 0.8; EIA_Code: E96; U/M: EA; AEC Category: Q200; Green_Lifecycle: Active; Green_REACh: Passed
R112 R113 = CSR1206FTR130: RES, 0.13, 1%, 0.5 W, 1206; Manufacturer: Stackpole Electronics Inc; CompType: Resistor; Value: 0.13; Value_Code: R130; Tolerance_%: 1; Power_W: 0.5; Value2: 0.5W; TempCo: 100 ppm/C; SizeArea_mm2: 5.12; SizeX_mm: 3.2; SizeY_mm: 1.6; SizeZ_mm: 1.35; EIA_Code: E96; U/M: EA; AEC Category: Q200
R114 = CRCW1206453KFKEA: RES, 453 k, 1%, 0.25 W, 1206; Manufacturer: Vishay-Dale; CompType: Resistor; Value: 453k; Res_ohm: 453000; Tolerance_%: 1; Power_W: 0.25; Value2: 0.25W; VDC_V: 200; TempCo: 100 ppm/C; SizeArea_mm2: 5.12; SizeX_mm: 3.2; SizeY_mm: 1.6; SizeZ_mm: 1.35; EIA_Code: E96; U/M: EA; AEC Category: Q200
R116 R123 = CRCW060375K0FKEA: RES, 75.0 k, 1%, 0.1 W, 0603; Manufacturer: Vishay-Dale; CompType: Resistor; Value: 75.0k; Res_ohm: 75000; Value_Code: 75k0; Tolerance_%: 1; Power_W: 0.1; Value2: 0.1W; VDC_V: 75; TempCo: 100 ppm/C; SizeArea_mm2: 1.28; SizeX_mm: 1.6; SizeY_mm: 0.8; EIA_Code: E96; U/M: EA; AEC Category: Q200; Green_Lifecycle: Active; Green_REACh: Passed
R117 = CRCW060336K5FKEA: RES, 36.5 k, 1%, 0.1 W, 0603; Manufacturer: Vishay-Dale; CompType: Resistor; Value: 36.5k; Res_ohm: 36500; Value_Code: 36k5; Tolerance_%: 1; Power_W: 0.1; Value2: 0.1W; VDC_V: 75; TempCo: 100 ppm/C; SizeArea_mm2: 1.28; SizeX_mm: 1.6; SizeY_mm: 0.8; EIA_Code: E96; U/M: EA; AEC Category: Q200; Green_Lifecycle: Active; Green_REACh: Passed
R118 = RC0603FR-07120KL: RES, 120 k, 1%, 0.1 W, 0603; Manufacturer: Yageo America; CompType: Resistor; Value: 120k; Res_ohm: 120000; Tolerance_%: 1; Power_W: 0.1; Value2: 0.1W; VDC_V: 150; TempCo: 200 ppm/C; SizeArea_mm2: 1.28; SizeX_mm: 1.6; SizeY_mm: 0.8; U/M: EA; AEC Category: Q200
R119 = CRCW060349K9FKEA: RES, 49.9 k, 1%, 0.1 W, 0603; Manufacturer: Vishay-Dale; CompType: Resistor; Value: 49.9k; Res_ohm: 49900; Value_Code: 49k9; Tolerance_%: 1; Power_W: 0.1; Value2: 0.1W; VDC_V: 75; TempCo: 100 ppm/C; SizeArea_mm2: 1.28; SizeX_mm: 1.6; SizeY_mm: 0.8; EIA_Code: E96; U/M: EA; AEC Category: Q200; Green_Lifecycle: Active; Green_REACh: Passed
R120 R124 = RC0603FR-07390KL: RES, 390 k, 1%, 0.1 W, 0603; Manufacturer: Yageo America; CompType: Resistor; Value: 390k; Res_ohm: 390000; Tolerance_%: 1; Power_W: 0.1; Value2: 0.1W; VDC_V: 150; TempCo: 200 ppm/C; SizeArea_mm2: 1.28; SizeX_mm: 1.6; SizeY_mm: 0.8; U/M: EA; AEC Category: Q200
R121 = CRCW080510R0FKEA: RES, 10.0, 1%, 0.125 W, 0805; Manufacturer: Vishay-Dale; CompType: Resistor; Value: 10.0; Res_ohm: 10; Value_Code: 10R0; Tolerance_%: 1; Power_W: 0.125; Value2: 0.125W; VDC_V: 150; TempCo: 100 ppm/C; SizeArea_mm2: 2.5; SizeX_mm: 2; SizeY_mm: 1.25; SizeZ_mm: 1.45; EIA_Code: E96; U/M: EA; AEC Category: Q200; Green_Lifecycle: Active; Green_REACh: Passed
R122 = RC0603FR-07180KL: RES, 180 k, 1%, 0.1 W, 0603; Manufacturer: Yageo America; CompType: Resistor; Value: 180k; Res_ohm: 180000; Tolerance_%: 1; Power_W: 0.1; Value2: 0.1W; VDC_V: 150; TempCo: 200 ppm/C; SizeArea_mm2: 1.28; SizeX_mm: 1.6; SizeY_mm: 0.8; U/M: EA; AEC Category: Q200; Green_Lifecycle: Active; Green_REACh: Passed
RT100 = B57236S0100M000: Thermistor NTC, 10 ohm, 20%, Disc_11.5mmx6mm; Manufacturer: TDK; Tolerance_%: 20; Power_W: 2.1; TaMin_C: -55; TaMax_C: 170; U/M: EA
RV100 = S10K275E2: Varistor 275V RMS 10MM Radial, TH; Manufacturer: EPCOS Inc; SymbolCreator: a0412235
TP_L = 5010: Test Point, Multipurpose, Red, TH; Manufacturer: Keystone; CompType: Test Point Loop; ContactFinish: Silver
TP_N = 5011: Test Point, Multipurpose, Black, TH; Manufacturer: Keystone; CompType: Test Point Loop; ContactFinish: Silver; Green_Lifecycle: Active; Green_REACh: Passed
TP_PE = 5012: Test Point, Multipurpose, White, TH; Manufacturer: Keystone; CompType: Test Point Loop; ContactFinish: Silver
U100 = UCC28056DBV: 6-Pin Single-Phase Transition-Mode PFC Controller, DBV0006A (SOT-23-6); Manufacturer: Texas Instruments; SymbolCreator: Altium; SizeArea_mm2: 8.12; SizeAreaWB_mm2: 14.82; SizeX_mm: 2.8; SizeY_mm: 2.9; SizeZ_mm: 1.45; CompType: IC; U/M: EA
